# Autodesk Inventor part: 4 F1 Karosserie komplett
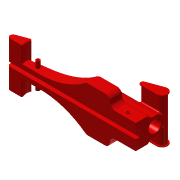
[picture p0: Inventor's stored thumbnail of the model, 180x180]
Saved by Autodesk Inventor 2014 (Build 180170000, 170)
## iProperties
Created: 2013-07
Part Number: 4 F1 Karosserie komplett
Material: Generisch
Document SubType Name: Modeling
Designer: Sofia
Density: 1 g/cm^3
Appearance: Rot
Author: Sofia
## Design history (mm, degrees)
sketch "Skizze1"
  geometry: L1 (0, 0)-(200, 0); L2 (200, 0)-(200, 20); L3 (200, 20)-(110, 20); L4 (0, 8)-(0, 0); A1 r 510.167 centre (110, -490.167) between (110, 20) and (0, 8)
  constraints: 8 end point, 2 perpendicular, 2 point on circle, 1 centre point, 1 horizontal, 1 parallel, 1 tangent
  dimensions: "d2" = 200 distance of L1.start L1.end; "d3" = 20 distance of L1.end L2.end; "d4" = 90 distance of L2.end L3.end; "d5" = 8 distance of L4.start L1.start
extrude "Extrusion1" new body sketch "Skizze1" distance "d6" = 35; taper "d7" = 0 deg
sketch "Skizze2"
  geometry: L1 (0, 0)-(200, 0) reference; L2 (0, 35)-(200, 35) reference; L3 (0, 0)-(0, 35) reference; L4 (0, 10)-(50, 10); L5 (200, 35)-(160, 35); L6 (160, 35)-(160, 19); L7 (160, 19)-(200, 19); L8 (200, 19)-(200, 35); A1 r 120 centre (50, 130) between (50, 10) and (123.314, 35)
  constraints: 10 end point, 2 parallel, 2 perpendicular, 2 point on circle, 2 point on line, 1 centre point, 1 horizontal, 1 tangent
  dimensions: "d8" = 50 distance of L4.start L4.end; "d9" = 10 distance between parallel lines of L4 L1; "d10" = 120 radius of A1; "d13" = 40 distance of L7.end L6.end; "d14" = 16 distance of L6.end L5.end
extrude "Extrusion2" cut sketch "Skizze2" stored distance "d15" = 35; taper "d16" = 0 deg
sketch "Skizze3"
  geometry: L1 (0, 0)-(0, 8) reference; L2 (50, 0)-(0, 0) reference; C1 r 3 at (40, 8)
  constraints: 1 centre point
  dimensions: "d17" = 6 diameter of C1; "d18" = 8 distance from line of C1.centre L2; "d19" = 40 distance from line of C1.centre L1
extrude "Extrusion3" join sketch "Skizze3" distance "d20" = 10; taper "d21" = 0 deg
hole "Bohrung1" diameter "d24" = 3; stored, may be unused: countersink angle "d28" = 90 deg, drill point angle "d30" = 118 deg; dims "d22" = 10, "d23" = 10, "d25" = 6, "d26" = 4, "d27" = 2, "d29" = 8
pattern_linear "Rechteckige Anordnung1"
fillet "Rundung1" dims "d34" = 8
mirror "Spiegeln1"
sketch "Skizze4"
  geometry: L1 (38, 0)-(0, 0) reference; L2 (38, 20)-(0, 20) reference; L3 (5, 20)-(5, 30); L4 (33, 30)-(33, 20); A1 r 14 centre (19, 30) between (33, 30) and (5, 30); 2 further points
  constraints: 4 end point, 2 perpendicular, 2 point on circle, 2 point on line, 2 tangent, 1 centre point, 1 midpoint, 1 vertical alignment
  dimensions: "d35" = 14 radius of A1; "d36" = 30 distance from line of A1.centre L1
extrude "Extrusion4" join sketch "Skizze4" distance "d37" = 80; taper "d38" = 0 deg
sketch "Skizze5"
  geometry: L1 (200, 0)-(0, 0) reference; L2 (0, 0)-(0, 8) reference; L3 (110, 20)-(120, 20) reference; L4 (120, 20)-(120, 44) reference; L5 (120, 44)-(200, 44) reference; L6 (200, 44)-(200, 0) reference; L7 (25.066, 17.123)-(0, 8); L8 (168.592, 41)-(193.592, 41); L9 (191.4, 53.43)-(167.908, 44.879); C1 r 1.5 at (180, 8) reference; C2 r 1.5 at (40, 8) reference; A1 r 510.167 centre (110, -490.167) between (110, 20) and (0, 8) reference; A2 r 17.5 centre (40, 8) between (25.066, 17.123) and (24.436, 0); A3 r 6.408 centre (193.592, 47.408) between (193.592, 41) and (191.4, 53.43); A4 r 2 centre (168.592, 43) between (167.908, 44.879) and (168.592, 41)
  constraints: 6 end point, 6 point on circle, 5 tangent, 3 centre point, 1 coincident, 1 perpendicular, 1 point on line
  dimensions: "d39" = 17.5 radius of A2; "d40" = 20 deg angle of L1 L7; "d41" = 20 deg angle of L8 L9; "d42" = 2 radius of A4; "d43" = 25 distance of L8.start L8.end; "d44" = 3 distance between parallel lines of L5 L8
  node "Schnittkanten projizieren1"
extrude "Extrusion5" join sketch "Skizze5" stored distance "d45" = 70; taper "d46" = 0 deg
extrude "Extrusion6" join sketch "Skizze5" stored distance "d47" = 70; taper "d48" = 0 deg
hole "Bohrung2" diameter "d51" = 19.5; stored, may be unused: countersink angle "d55" = 90 deg, drill point angle "d57" = 118 deg; dims "d49" = 10, "d50" = 10, "d52" = 6, "d53" = 4, "d54" = 2, "d56" = 55
sketch "Skizze6"
  geometry: L1 (200, 0)-(0, 0) reference; L2 (0, 0)-(0, 8) reference; L3 (0, 8)-(25.066, 17.123) reference; L4 (110, 20)-(120, 20) reference; L5 (120, 20)-(120, 44) reference; L6 (120, 44)-(166.86, 44) reference; L7 (167.908, 44.879)-(191.4, 53.43) reference; L8 (199.019, 44)-(200, 44) reference; L9 (200, 44)-(200, 39.75) reference; L10 (200, 39.75)-(145, 39.75) reference; L11 (145, 39.75)-(139.142, 30) reference; L12 (139.142, 30)-(145, 20.25) reference; L13 (145, 20.25)-(200, 20.25) reference; L14 (200, 20.25)-(200, 0) reference; L15 (120, 20)-(133.856, 44); C1 r 1.5 at (180, 8) reference; C2 r 1.5 at (40, 8) reference; A1 r 17.5 centre (40, 8) between (25.066, 17.123) and (23.1, 12.544) reference; A2 r 510.167 centre (110, -490.167) between (110, 20) and (23.1, 12.544) reference; A3 r 2 centre (168.592, 43) between (167.908, 44.879) and (166.86, 44) reference; A4 r 6.408 centre (193.592, 47.408) between (199.019, 44) and (191.4, 53.43) reference
  constraints: 2 end point, 1 point on line
  dimensions: "d58" = 30 deg angle of L5 L15
extrude "Extrusion7" cut sketch "Skizze6" stored distance "d59" = 10; taper "d60" = 0 deg
sketch "Skizze7"
  geometry: L1 (168.592, 41)-(193.592, 41) reference; L2 (191.4, 53.43)-(167.908, 44.879) reference; L3 (167.224, 46.759)-(190.716, 55.309); L4 (193.592, 39)-(168.592, 39); A1 r 6.408 centre (193.592, 47.408) between (193.592, 41) and (191.4, 53.43) reference; A2 r 2 centre (168.592, 43) between (167.908, 44.879) and (168.592, 41) reference; A3 r 8.408 centre (193.592, 47.408) between (193.592, 39) and (190.716, 55.309); A4 r 4 centre (168.592, 43) between (167.224, 46.759) and (168.592, 39); 1 further point
  constraints: 4 end point, 4 point on circle, 2 centre point, 3 other
  dimensions: "d61" = 2 distance between parallel lines of L3 L2
extrude "Extrusion8" join sketch "Skizze7" distance "d62" = 1; taper "d63" = 0 deg
mirror "Spiegeln2"
fillet "Rundung2"
fillet "Rundung3" dims "d64" = 2
fillet "Rundung4" dims "d65" = 7
sketch "Skizze8"
  geometry: L1 (38, 0)-(0, 0) reference; L2 (16, 6)-(22, 6); L3 (22, 6)-(22, 0); L4 (22, 0)-(16, 0); L5 (16, 0)-(16, 6); 2 further points
  constraints: 8 end point, 2 midpoint, 2 parallel, 1 horizontal, 1 perpendicular
  dimensions: "d66" = 6 distance of L3.end L4.end; "d67" = 6 distance of L2.end L3.end
extrude "Extrusion9" cut sketch "Skizze8" stored distance "d68" = 1; taper "d69" = 0 deg
node "Volumenkörper1"
node "Schnittkanten projizieren2"
